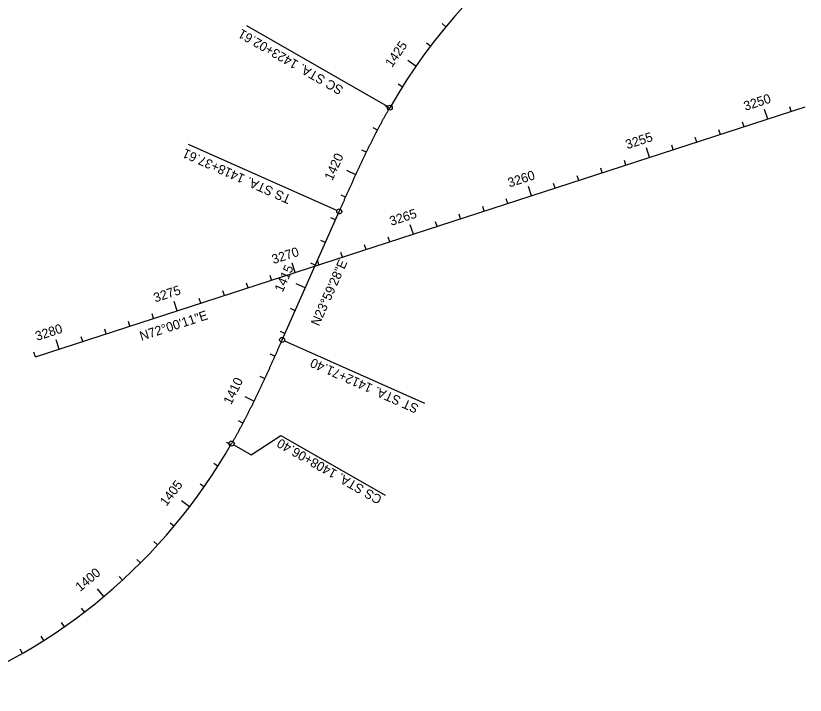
# Model space of a CAD drawing. Extents: x 1280727 to 1452510, y 526233 to 601451.
# Drawn here: x 1397990 to 1401168, y 573188 to 575925 of the extents above; entities that cross this region are included whole.
import ezdxf

# ---------------------------------------------------------------- set-up
doc = ezdxf.new("R2010")
doc.units = 0
for name, color, linetype in [('RW_X_CL', 7, 'Continuous'), ('RW_X_CL_500_Stations', 7, 'Continuous'), ('SH_Text', 7, 'Continuous')]:
    doc.layers.add(name, color=color, linetype=linetype)

msp = doc.modelspace()

# ---------------------------------------------------------------- linework, layer by layer
at = {"layer": 'RW_X_CL'}
for p, q in [((1398068.9, 574551.5), (1401168.4, 575558.4)), ((1399062.1, 574620), (1399292.3, 575137.3))]:
    msp.add_line(p, q, dxfattribs=at)
for centre, start, end in [((1401484.2, 574416.2), 98.7581, 150.1964), ((1396870.1, 575341.1), 290.0679, 330.1964)]:
    msp.add_arc(centre, 2291.8, start, end, dxfattribs=at)
for points in [[(1399292.3, 575137.3), (1399294.8, 575143.1), (1399297.4, 575148.8), (1399299.9, 575154.6), (1399302.5, 575160.3), (1399305.1, 575166), (1399307.6, 575171.8), (1399310.2, 575177.5), (1399312.7, 575183.3), (1399315.3, 575189), (1399317.9, 575194.7), (1399320.4, 575200.5), (1399323, 575206.2), (1399325.6, 575211.9), (1399328.1, 575217.7), (1399330.7, 575223.4), (1399333.3, 575229.1), (1399335.9, 575234.8), (1399338.5, 575240.6), (1399341.1, 575246.3), (1399343.7, 575252), (1399346.3, 575257.7), (1399348.9, 575263.5), (1399351.5, 575269.2), (1399354.1, 575274.9), (1399356.7, 575280.6), (1399359.3, 575286.3), (1399362, 575292), (1399364.6, 575297.7), (1399367.2, 575303.4), (1399369.9, 575309.1), (1399372.5, 575314.8), (1399375.2, 575320.5), (1399377.9, 575326.2), (1399380.5, 575331.9), (1399383.2, 575337.6), (1399385.9, 575343.3), (1399388.6, 575348.9), (1399391.3, 575354.6), (1399394, 575360.3), (1399396.7, 575365.9), (1399399.5, 575371.6), (1399402.2, 575377.3), (1399404.9, 575382.9), (1399407.7, 575388.6), (1399410.5, 575394.2), (1399413.2, 575399.8), (1399416, 575405.5), (1399418.8, 575411.1), (1399421.6, 575416.7), (1399424.4, 575422.3), (1399427.3, 575428), (1399430.1, 575433.6), (1399432.9, 575439.2), (1399435.8, 575444.8), (1399438.7, 575450.4), (1399441.5, 575455.9), (1399444.4, 575461.5), (1399447.3, 575467.1), (1399450.2, 575472.7), (1399453.2, 575478.2), (1399456.1, 575483.8), (1399459.1, 575489.3), (1399462, 575494.9), (1399465, 575500.4), (1399468, 575505.9), (1399471, 575511.5), (1399474, 575517), (1399477, 575522.5), (1399480.1, 575528), (1399483.1, 575533.5), (1399486.2, 575538.9), (1399489.3, 575544.4), (1399492.4, 575549.9), (1399495.5, 575555.3)], [(1399062.1, 574620), (1399059.5, 574614.3), (1399057, 574608.6), (1399054.4, 574602.8), (1399051.8, 574597.1), (1399049.3, 574591.3), (1399046.7, 574585.6), (1399044.2, 574579.9), (1399041.6, 574574.1), (1399039, 574568.4), (1399036.5, 574562.6), (1399033.9, 574556.9), (1399031.3, 574551.2), (1399028.8, 574545.4), (1399026.2, 574539.7), (1399023.6, 574534), (1399021, 574528.2), (1399018.5, 574522.5), (1399015.9, 574516.8), (1399013.3, 574511.1), (1399010.7, 574505.3), (1399008.1, 574499.6), (1399005.5, 574493.9), (1399002.9, 574488.2), (1399000.3, 574482.5), (1398997.6, 574476.8), (1398995, 574471.1), (1398992.4, 574465.3), (1398989.7, 574459.6), (1398987.1, 574453.9), (1398984.5, 574448.2), (1398981.8, 574442.5), (1398979.1, 574436.9), (1398976.5, 574431.2), (1398973.8, 574425.5), (1398971.1, 574419.8), (1398968.4, 574414.1), (1398965.7, 574408.4), (1398963, 574402.8), (1398960.3, 574397.1), (1398957.6, 574391.4), (1398954.9, 574385.8), (1398952.1, 574380.1), (1398949.4, 574374.5), (1398946.6, 574368.8), (1398943.9, 574363.2), (1398941.1, 574357.5), (1398938.3, 574351.9), (1398935.5, 574346.3), (1398932.7, 574340.6), (1398929.9, 574335), (1398927.1, 574329.4), (1398924.3, 574323.8), (1398921.4, 574318.2), (1398918.6, 574312.6), (1398915.7, 574307), (1398912.8, 574301.4), (1398909.9, 574295.8), (1398907, 574290.3), (1398904.1, 574284.7), (1398901.2, 574279.1), (1398898.2, 574273.6), (1398895.3, 574268), (1398892.3, 574262.5), (1398889.3, 574257), (1398886.4, 574251.4), (1398883.4, 574245.9), (1398880.3, 574240.4), (1398877.3, 574234.9), (1398874.3, 574229.4), (1398871.2, 574223.9), (1398868.1, 574218.4), (1398865.1, 574213), (1398862, 574207.5), (1398858.8, 574202)]]:
    msp.add_spline(points, degree=3, dxfattribs=at)
at = {"layer": 'RW_X_CL_500_Stations'}
for p, q in [((1399721.9, 575881.4), (1399706.5, 575894.1)), ((1399659.6, 575803.1), (1399643.7, 575815.2)), ((1399600.9, 575722.2), (1399568, 575745)), ((1399545.7, 575638.8), (1399528.8, 575649.5)), ((1399494.2, 575553.1), (1399476.8, 575563)), ((1401112.4, 575540.2), (1401106.2, 575559.2)), ((1401017.3, 575509.3), (1401004.9, 575547.3)), ((1400922.2, 575478.4), (1400916, 575497.4)), ((1399446.4, 575465.3), (1399428.6, 575474.5)), ((1400827.1, 575447.5), (1400820.9, 575466.5)), ((1400731.9, 575416.6), (1400725.8, 575435.6)), ((1400636.8, 575385.7), (1400630.7, 575404.7)), ((1399401.5, 575375.9), (1399383.5, 575384.6)), ((1400541.7, 575354.8), (1400529.4, 575392.9)), ((1400446.6, 575323.9), (1400440.4, 575342.9)), ((1399358.9, 575285.4), (1399322.6, 575302.1)), ((1400351.5, 575293), (1400345.3, 575312)), ((1400256.4, 575262.1), (1400250.2, 575281.1)), ((1400066.2, 575200.3), (1400053.8, 575238.4)), ((1400161.3, 575231.2), (1400155.1, 575250.2)), ((1399317.7, 575194.3), (1399299.4, 575202.5)), ((1399971.1, 575169.4), (1399964.9, 575188.5)), ((1399876, 575138.5), (1399869.8, 575157.6)), ((1399277, 575103), (1399258.7, 575111.1)), ((1399780.9, 575107.6), (1399774.7, 575126.7)), ((1399590.7, 575045.8), (1399578.3, 575083.9)), ((1399685.8, 575076.7), (1399679.6, 575095.8)), ((1399236.3, 575011.6), (1399218.1, 575019.7)), ((1399495.6, 575014.9), (1399489.4, 575034)), ((1399400.4, 574984), (1399394.3, 575003.1)), ((1399305.3, 574953.2), (1399299.2, 574972.2)), ((1399115.1, 574891.4), (1399102.8, 574929.4)), ((1399195.7, 574920.3), (1399177.4, 574928.4)), ((1399210.2, 574922.3), (1399204.1, 574941.3)), ((1399020, 574860.5), (1399013.8, 574879.5)), ((1398924.9, 574829.6), (1398918.7, 574848.6)), ((1399155, 574828.9), (1399118.5, 574845.2)), ((1398829.8, 574798.7), (1398823.6, 574817.7)), ((1398639.6, 574736.9), (1398627.2, 574774.9)), ((1398734.7, 574767.8), (1398728.5, 574786.8)), ((1399114.4, 574737.5), (1399096.1, 574745.7)), ((1398449.4, 574675.1), (1398443.2, 574694.1)), ((1398544.5, 574706), (1398538.3, 574725)), ((1398354.3, 574644.2), (1398348.1, 574663.2)), ((1398259.2, 574613.3), (1398253, 574632.3)), ((1399073.7, 574646.2), (1399055.4, 574654.3)), ((1398164.1, 574582.4), (1398151.7, 574620.4)), ((1398068.9, 574551.5), (1398062.8, 574570.5)), ((1399033, 574554.8), (1399014.7, 574563)), ((1398991.7, 574463.8), (1398973.5, 574472.2)), ((1398948.9, 574373.4), (1398912.9, 574390.9)), ((1398903.8, 574284.1), (1398886.1, 574293.4)), ((1398855.6, 574196.5), (1398838.3, 574206.5)), ((1398803.8, 574111), (1398787, 574121.7)), ((1398748.3, 574027.8), (1398731.9, 574039.3)), ((1398689.3, 573947.1), (1398657.5, 573971.4)), ((1398626.7, 573869.1), (1398611.4, 573881.9)), ((1398560.8, 573793.9), (1398546.1, 573807.4)), ((1398491.7, 573721.6), (1398477.6, 573735.7)), ((1398419.5, 573652.4), (1398406, 573667.1)), ((1398344.4, 573586.4), (1398318.7, 573617.1)), ((1398266.5, 573523.8), (1398254.3, 573539.7)), ((1398185.9, 573464.6), (1398174.4, 573481)), ((1398102.8, 573409), (1398092, 573425.9)), ((1398017.3, 573357.1), (1398007.3, 573374.4))]:
    msp.add_line(p, q, dxfattribs=at)
at = {"layer": 'SH_Text'}
for p, q in [((1399486.8, 575560.3), (1398920.2, 575884.9)), ((1399283.1, 575141.4), (1398685.8, 575407.2)), ((1399071.2, 574616), (1399636.1, 574364.6)), ((1398936.9, 574157.3), (1399057.6, 574235.1)), ((1399057.6, 574235.1), (1399477, 573994.9)), ((1398867.5, 574197.1), (1398936.9, 574157.3))]:
    msp.add_line(p, q, dxfattribs=at)
for centre in [(1399495.5, 575555.3), (1399292.3, 575137.3), (1399062.1, 574620), (1398858.8, 574202)]:
    msp.add_circle(centre, 10, dxfattribs=at)

# ---------------------------------------------------------------- texts
at = {"layer": 'RW_X_CL_500_Stations'}
for s, rotation, p in [('1425', 55.2616, (1399504.7, 575714.9)), ('3250', 17.997, (1400927.7, 575542.3)), ('3255', 17.997, (1400451.8, 575387.7)), ('1420', 65.3, (1399264.3, 575259.2)), ('3260', 17.997, (1399977.6, 575233.6)), ('3265', 17.997, (1399501.7, 575079)), ('3270', 17.997, (1399027.4, 574924.9)), ('1415', 66.0089, (1399064.1, 574809.1)), ('3275', 17.997, (1398551.4, 574770.3)), ('3280', 17.997, (1398075.1, 574615.6)), ('1410', 64.0289, (1398857.2, 574356.3)), ('1405', 52.5365, (1398596.2, 573947.3)), ('1400', 40.0365, (1398249.2, 573604.3))]:
    msp.add_text(s, height=37.5, rotation=rotation, dxfattribs=at).set_placement(p)
at = {"layer": 'SH_Text'}
for s, rotation, p in [('SC STA. 1423+02.61', 150.1964, (1399312, 575637.4)), ('TS STA. 1418+37.61', 156.0089, (1399101.4, 575200.4)), ('N23°59\'28"E', 66.0089, (1399210.4, 574672.7)), ('N72°00\'11"E', 17.997, (1398495.6, 574615.9)), ('ST STA. 1412+71.40', 156.0089, (1399615.6, 574356.6)), ('CS STA. 1408+06.40', 150.1964, (1399467.9, 573988))]:
    msp.add_text(s, height=37.5, rotation=rotation, dxfattribs=at).set_placement(p)

doc.saveas('drawing.dxf')
